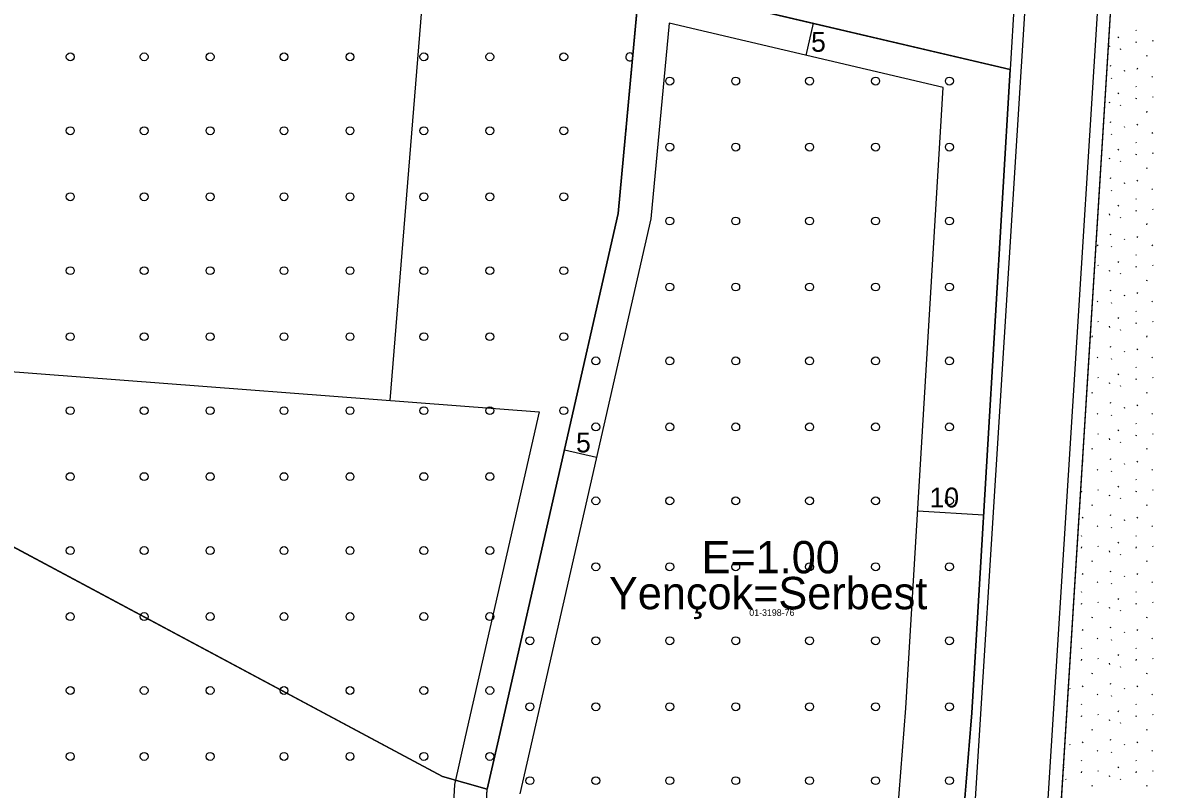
# Model space of a CAD drawing. Extents: x 419396 to 421519, y 4453567 to 4456767.
# Drawn here: x 420389.1 to 420561.7, y 4455467.4 to 4455583.5 of the extents above; entities that cross this region are included whole.
import ezdxf

# ---------------------------------------------------------------- set-up
doc = ezdxf.new("R2010")
doc.units = 0
for name, color, linetype in [('0_KADASTRO', 7, 'Continuous'), ('@PL', 7, 'Continuous'), ('ADAKENARI1000', 7, 'Continuous'), ('F_YAPI_YAKLAŞMA', 7, 'Continuous'), ('KALDIRIM', 7, 'Continuous'), ('Level 33', 7, 'Continuous'), ('Level 41', 7, 'Continuous')]:
    doc.layers.add(name, color=color, linetype=linetype)

msp = doc.modelspace()

# ---------------------------------------------------------------- linework, layer by layer
at = {"layer": '0_KADASTRO'}
for p, q in [((420452.76, 4455469.35), (420330.1, 4455534.91)), ((420459.55, 4455467.41), (420452.76, 4455469.35)), ((420458.85, 4455454.77), (420459.55, 4455467.41))]:
    msp.add_line(p, q, dxfattribs=at)
for points in [[(420545.42, 4455447.04), (420561.03, 4455696.59), (420608.27, 4455685.53), (420614.84, 4455734.09), (420621.11, 4455745.07), (420621.38, 4455786.21), (420636.29, 4455823.29), (420701.58, 4455861.23), (420708.62, 4455863.92), (420715.79, 4455864.57), (420723.78, 4455862.78), (420730.13, 4455859.19), (420735, 4455853.4), (420771.9, 4455797.51), (420787.06, 4455778.4), (420884.04, 4455668.02), (420888.93, 4455658.72), (420890.16, 4455653.06), (420890.46, 4455645.52), (420886.58, 4455581.52), (420884.98, 4455552.19), (420718.56, 4455563.04), (420710.4, 4455437.34), (420549.3, 4455446.81)], [(420275.85, 4455671.09), (420269.39, 4455564.37), (420295.04, 4455552.07), (420330.1, 4455534.91), (420452.76, 4455469.35), (420459.55, 4455467.41), (420461.1, 4455474.22), (420479.42, 4455554.65), (420482.66, 4455589.64), (420486.7, 4455626.91), (420281.84, 4455680.27)], [(420458.85, 4455454.77), (420459.55, 4455467.41), (420461.1, 4455474.22), (420479.42, 4455554.65), (420482.66, 4455589.64), (420538.83, 4455576.49), (420533.01, 4455478.98), (420530.71, 4455450.63), (420530.12, 4455445.17), (420528.73, 4455440.39), (420525.87, 4455433.63)]]:
    msp.add_lwpolyline(points, close=True, dxfattribs=at)
at = {"layer": 'ADAKENARI1000'}
for p, q in [((420545.42, 4455447.04), (420561.03, 4455696.59)), ((420544.5, 4455671.29), (420538.83, 4455576.49)), ((420482.66, 4455589.65), (420479.42, 4455554.65)), ((420538.83, 4455576.49), (420482.66, 4455589.65)), ((420533.01, 4455478.98), (420538.83, 4455576.49)), ((420479.42, 4455554.65), (420461.1, 4455474.22)), ((420530.71, 4455450.63), (420533.01, 4455478.98)), ((420461.1, 4455474.22), (420459.55, 4455467.41))]:
    msp.add_line(p, q, dxfattribs=at)
at = {"layer": 'F_YAPI_YAKLAŞMA'}
for p, q in [((420451.96, 4455614.64), (420444.78, 4455526.32)), ((420487.11, 4455583.47), (420484.37, 4455553.86)), ((420528.65, 4455573.74), (420487.11, 4455583.47)), ((420507.88, 4455578.6), (420509.02, 4455583.47)), ((420523.03, 4455479.68), (420528.65, 4455573.74)), ((420484.37, 4455553.86), (420465.97, 4455473.11)), ((420302.87, 4455537.14), (420467.44, 4455524.59)), ((420467.44, 4455524.59), (420456.23, 4455475.33)), ((420476.13, 4455517.69), (420471.25, 4455518.8)), ((420524.82, 4455509.58), (420534.8, 4455508.98)), ((420520.76, 4455451.57), (420523.03, 4455479.68)), ((420456.23, 4455475.33), (420454.58, 4455468.1)), ((420465.97, 4455473.11), (420464.51, 4455466.71)), ((420454.58, 4455468.1), (420453.79, 4455453.91))]:
    msp.add_line(p, q, dxfattribs=at)
at = {"layer": 'KALDIRIM'}
for p, q in [((420532.5, 4455448.73), (420548.29, 4455701.05)), ((420543.48, 4455448.05), (420559.3, 4455700.93))]:
    msp.add_line(p, q, dxfattribs=at)
at = {"layer": 'Level 33'}
for centre in [(420396.35, 4455578.38), (420407.55, 4455578.38), (420417.55, 4455578.38), (420428.75, 4455578.38), (420438.75, 4455578.38), (420449.95, 4455578.38), (420459.95, 4455578.38), (420471.15, 4455578.38), (420487.22, 4455574.71), (420497.22, 4455574.71), (420508.42, 4455574.71), (420518.42, 4455574.71), (420529.62, 4455574.71), (420396.35, 4455567.18), (420407.55, 4455567.18), (420417.55, 4455567.18), (420428.75, 4455567.18), (420438.75, 4455567.18), (420449.95, 4455567.18), (420459.95, 4455567.18), (420471.15, 4455567.18), (420487.22, 4455564.71), (420497.22, 4455564.71), (420508.42, 4455564.71), (420518.42, 4455564.71), (420529.62, 4455564.71), (420396.35, 4455557.18), (420407.55, 4455557.18), (420417.55, 4455557.18), (420428.75, 4455557.18), (420438.75, 4455557.18), (420449.95, 4455557.18), (420459.95, 4455557.18), (420471.15, 4455557.18), (420487.22, 4455553.51), (420497.22, 4455553.51), (420508.42, 4455553.51), (420518.42, 4455553.51), (420529.62, 4455553.51), (420396.35, 4455545.98), (420407.55, 4455545.98), (420417.55, 4455545.98), (420428.75, 4455545.98), (420438.75, 4455545.98), (420449.95, 4455545.98), (420459.95, 4455545.98), (420471.15, 4455545.98), (420487.22, 4455543.51), (420497.22, 4455543.51), (420508.42, 4455543.51), (420518.42, 4455543.51), (420529.62, 4455543.51), (420396.35, 4455535.98), (420407.55, 4455535.98), (420417.55, 4455535.98), (420428.75, 4455535.98), (420438.75, 4455535.98), (420449.95, 4455535.98), (420459.95, 4455535.98), (420471.15, 4455535.98), (420476.02, 4455532.31), (420487.22, 4455532.31), (420497.22, 4455532.31), (420508.42, 4455532.31), (420518.42, 4455532.31), (420529.62, 4455532.31), (420396.35, 4455524.77), (420407.55, 4455524.77), (420417.55, 4455524.77), (420428.75, 4455524.77), (420438.75, 4455524.77), (420449.95, 4455524.77), (420459.95, 4455524.77), (420471.15, 4455524.77), (420476.02, 4455522.31), (420487.22, 4455522.31), (420497.22, 4455522.31), (420508.42, 4455522.31), (420518.42, 4455522.31), (420529.62, 4455522.31), (420396.35, 4455514.77), (420407.55, 4455514.77), (420417.55, 4455514.77), (420428.75, 4455514.77), (420438.75, 4455514.77), (420449.95, 4455514.77), (420459.95, 4455514.77), (420476.02, 4455511.11), (420487.22, 4455511.11), (420497.22, 4455511.11), (420508.42, 4455511.11), (420518.42, 4455511.11), (420529.62, 4455511.11), (420396.35, 4455503.57), (420407.55, 4455503.57), (420417.55, 4455503.57), (420428.75, 4455503.57), (420438.75, 4455503.57), (420449.95, 4455503.57), (420459.95, 4455503.57), (420476.02, 4455501.11), (420487.22, 4455501.11), (420497.22, 4455501.11), (420508.42, 4455501.11), (420518.42, 4455501.11), (420529.62, 4455501.11), (420396.35, 4455493.57), (420407.55, 4455493.57), (420417.55, 4455493.57), (420428.75, 4455493.57), (420438.75, 4455493.57), (420449.95, 4455493.57), (420459.95, 4455493.57), (420466.02, 4455489.9), (420476.02, 4455489.9), (420487.22, 4455489.9), (420497.22, 4455489.9), (420508.42, 4455489.9), (420518.42, 4455489.9), (420529.62, 4455489.9), (420396.35, 4455482.37), (420407.55, 4455482.37), (420417.55, 4455482.37), (420428.75, 4455482.37), (420438.75, 4455482.37), (420449.95, 4455482.37), (420459.95, 4455482.37), (420466.02, 4455479.9), (420476.02, 4455479.9), (420487.22, 4455479.9), (420497.22, 4455479.9), (420508.42, 4455479.9), (420518.42, 4455479.9), (420529.62, 4455479.9), (420396.35, 4455472.37), (420407.55, 4455472.37), (420417.55, 4455472.37), (420428.75, 4455472.37), (420438.75, 4455472.37), (420449.95, 4455472.37), (420459.95, 4455472.37), (420466.02, 4455468.7), (420476.02, 4455468.7), (420487.22, 4455468.7), (420497.22, 4455468.7), (420508.42, 4455468.7), (420518.42, 4455468.7), (420529.62, 4455468.7)]:
    msp.add_circle(centre, 0.6, dxfattribs=at)
for centre, start, end in [((420481.15, 4455578.38), 33.6502, 315.7609), ((420481.15, 4455567.18), 155.5882, 193.8229)]:
    msp.add_arc(centre, 0.6, start, end, dxfattribs=at)
at = {"layer": 'Level 41'}
for p, q in [((420557.86, 4455582.46), (420557.93, 4455582.36)), ((420555.22, 4455581.27), (420555.29, 4455581.43)), ((420557.92, 4455580.54), (420557.99, 4455580.7)), ((420560.38, 4455580.89), (420560.45, 4455580.78)), ((420553.85, 4455580.1), (420553.87, 4455579.94)), ((420555.48, 4455579.63), (420555.55, 4455579.52)), ((420559.53, 4455578.48), (420559.61, 4455578.64)), ((420554.01, 4455576.95), (420554.08, 4455577.11)), ((420554.12, 4455575.21), (420554.19, 4455575.11)), ((420556.11, 4455576.34), (420556.18, 4455576.23)), ((420558.1, 4455576.54), (420558.17, 4455576.7)), ((420560.32, 4455575.41), (420560.39, 4455575.3)), ((420557.86, 4455573.95), (420557.93, 4455573.85)), ((420553.85, 4455571.59), (420553.87, 4455571.43)), ((420555.22, 4455572.76), (420555.29, 4455572.92)), ((420557.92, 4455572.03), (420557.99, 4455572.19)), ((420560.38, 4455572.38), (420560.45, 4455572.27)), ((420555.48, 4455571.12), (420555.55, 4455571.01)), ((420559.53, 4455569.97), (420559.61, 4455570.13)), ((420554.01, 4455568.44), (420554.08, 4455568.6)), ((420558.1, 4455568.03), (420558.17, 4455568.19)), ((420554.12, 4455566.7), (420554.19, 4455566.6)), ((420556.11, 4455567.83), (420556.18, 4455567.72)), ((420560.32, 4455566.9), (420560.39, 4455566.79)), ((420557.86, 4455565.44), (420557.93, 4455565.34)), ((420553.85, 4455563.08), (420553.87, 4455562.92)), ((420555.22, 4455564.25), (420555.29, 4455564.41)), ((420557.92, 4455563.52), (420557.99, 4455563.68)), ((420560.38, 4455563.87), (420560.45, 4455563.76)), ((420555.48, 4455562.61), (420555.55, 4455562.5)), ((420559.53, 4455561.46), (420559.61, 4455561.62)), ((420554.01, 4455559.93), (420554.08, 4455560.09)), ((420558.1, 4455559.52), (420558.17, 4455559.68)), ((420554.12, 4455558.19), (420554.19, 4455558.09)), ((420556.11, 4455559.32), (420556.18, 4455559.21)), ((420560.32, 4455558.39), (420560.39, 4455558.28)), ((420557.86, 4455556.93), (420557.93, 4455556.83)), ((420553.85, 4455554.57), (420553.87, 4455554.41)), ((420555.22, 4455555.74), (420555.29, 4455555.9)), ((420557.92, 4455555.01), (420557.99, 4455555.17)), ((420560.38, 4455555.36), (420560.45, 4455555.25)), ((420555.48, 4455554.1), (420555.55, 4455553.99)), ((420559.53, 4455552.95), (420559.61, 4455553.11)), ((420554.01, 4455551.42), (420554.08, 4455551.58)), ((420558.1, 4455551.01), (420558.17, 4455551.17)), ((420552.02, 4455549.88), (420552.09, 4455549.77)), ((420554.12, 4455549.68), (420554.19, 4455549.58)), ((420556.11, 4455550.81), (420556.18, 4455550.7)), ((420560.32, 4455549.88), (420560.39, 4455549.77)), ((420557.86, 4455548.42), (420557.93, 4455548.32)), ((420552.09, 4455546.85), (420552.16, 4455546.74)), ((420553.85, 4455546.06), (420553.87, 4455545.9)), ((420555.22, 4455547.23), (420555.29, 4455547.39)), ((420557.92, 4455546.5), (420557.99, 4455546.66)), ((420560.38, 4455546.85), (420560.45, 4455546.74)), ((420555.48, 4455545.59), (420555.55, 4455545.48)), ((420559.53, 4455544.44), (420559.61, 4455544.6)), ((420554.01, 4455542.91), (420554.08, 4455543.07)), ((420556.11, 4455542.3), (420556.18, 4455542.19)), ((420558.1, 4455542.5), (420558.17, 4455542.66)), ((420552.02, 4455541.37), (420552.09, 4455541.26)), ((420554.12, 4455541.17), (420554.19, 4455541.07)), ((420560.32, 4455541.37), (420560.39, 4455541.26)), ((420555.22, 4455538.72), (420555.29, 4455538.88)), ((420557.86, 4455539.91), (420557.93, 4455539.81)), ((420552.09, 4455538.34), (420552.16, 4455538.23)), ((420553.85, 4455537.55), (420553.87, 4455537.39)), ((420555.48, 4455537.08), (420555.55, 4455536.97)), ((420557.92, 4455537.99), (420557.99, 4455538.15)), ((420560.38, 4455538.34), (420560.45, 4455538.23)), ((420551.24, 4455535.93), (420551.31, 4455536.09)), ((420559.53, 4455535.93), (420559.61, 4455536.09)), ((420554.01, 4455534.4), (420554.08, 4455534.56)), ((420556.11, 4455533.79), (420556.18, 4455533.68)), ((420558.1, 4455533.99), (420558.17, 4455534.15)), ((420552.02, 4455532.86), (420552.09, 4455532.75)), ((420554.12, 4455532.66), (420554.19, 4455532.56)), ((420560.32, 4455532.86), (420560.39, 4455532.75)), ((420555.22, 4455530.21), (420555.29, 4455530.37)), ((420557.86, 4455531.4), (420557.93, 4455531.3)), ((420552.09, 4455529.83), (420552.16, 4455529.72)), ((420553.85, 4455529.04), (420553.87, 4455528.88)), ((420555.48, 4455528.57), (420555.55, 4455528.46)), ((420557.92, 4455529.48), (420557.99, 4455529.64)), ((420560.38, 4455529.83), (420560.45, 4455529.72)), ((420551.24, 4455527.42), (420551.31, 4455527.58)), ((420559.53, 4455527.42), (420559.61, 4455527.58)), ((420554.01, 4455525.89), (420554.08, 4455526.05)), ((420556.11, 4455525.28), (420556.18, 4455525.17)), ((420558.1, 4455525.48), (420558.17, 4455525.64)), ((420552.02, 4455524.35), (420552.09, 4455524.24)), ((420554.12, 4455524.15), (420554.19, 4455524.05)), ((420560.32, 4455524.35), (420560.39, 4455524.24)), ((420555.22, 4455521.7), (420555.29, 4455521.86)), ((420557.86, 4455522.89), (420557.93, 4455522.79)), ((420552.09, 4455521.32), (420552.16, 4455521.21)), ((420553.85, 4455520.53), (420553.87, 4455520.37)), ((420555.48, 4455520.06), (420555.55, 4455519.95)), ((420557.92, 4455520.97), (420557.99, 4455521.13)), ((420560.38, 4455521.32), (420560.45, 4455521.21)), ((420551.24, 4455518.91), (420551.31, 4455519.07)), ((420559.53, 4455518.91), (420559.61, 4455519.07)), ((420549.8, 4455516.97), (420549.87, 4455517.13)), ((420554.01, 4455517.38), (420554.08, 4455517.54)), ((420556.11, 4455516.77), (420556.18, 4455516.66)), ((420558.1, 4455516.97), (420558.17, 4455517.13)), ((420552.02, 4455515.84), (420552.09, 4455515.73)), ((420554.12, 4455515.64), (420554.19, 4455515.54)), ((420560.32, 4455515.84), (420560.39, 4455515.73)), ((420549.63, 4455514.3), (420549.64, 4455514.28)), ((420555.22, 4455513.19), (420555.29, 4455513.35)), ((420557.86, 4455514.38), (420557.93, 4455514.28)), ((420549.63, 4455512.46), (420549.7, 4455512.62)), ((420552.09, 4455512.81), (420552.16, 4455512.7)), ((420553.85, 4455512.02), (420553.87, 4455511.86)), ((420555.48, 4455511.55), (420555.55, 4455511.44)), ((420557.92, 4455512.46), (420557.99, 4455512.62)), ((420560.38, 4455512.81), (420560.45, 4455512.7)), ((420551.24, 4455510.4), (420551.31, 4455510.56)), ((420559.53, 4455510.4), (420559.61, 4455510.56)), ((420549.8, 4455508.46), (420549.87, 4455508.62)), ((420554.01, 4455508.87), (420554.08, 4455509.03)), ((420556.11, 4455508.26), (420556.18, 4455508.15)), ((420558.1, 4455508.46), (420558.17, 4455508.62)), ((420552.02, 4455507.33), (420552.09, 4455507.22)), ((420554.12, 4455507.13), (420554.19, 4455507.03)), ((420560.32, 4455507.33), (420560.39, 4455507.22)), ((420549.57, 4455505.87), (420549.64, 4455505.77)), ((420552.09, 4455504.3), (420552.16, 4455504.19)), ((420555.22, 4455504.68), (420555.29, 4455504.84)), ((420557.86, 4455505.87), (420557.93, 4455505.77)), ((420560.38, 4455504.3), (420560.45, 4455504.19)), ((420549.63, 4455503.95), (420549.7, 4455504.11)), ((420553.85, 4455503.51), (420553.87, 4455503.35)), ((420555.48, 4455503.04), (420555.55, 4455502.93)), ((420557.92, 4455503.95), (420557.99, 4455504.11)), ((420551.24, 4455501.89), (420551.31, 4455502.05)), ((420559.53, 4455501.89), (420559.61, 4455502.05)), ((420549.8, 4455499.95), (420549.87, 4455500.11)), ((420554.01, 4455500.36), (420554.08, 4455500.52)), ((420556.11, 4455499.75), (420556.18, 4455499.64)), ((420558.1, 4455499.95), (420558.17, 4455500.11)), ((420552.02, 4455498.82), (420552.09, 4455498.71)), ((420554.12, 4455498.62), (420554.19, 4455498.52)), ((420560.32, 4455498.82), (420560.39, 4455498.71)), ((420549.57, 4455497.36), (420549.64, 4455497.26)), ((420552.09, 4455495.79), (420552.16, 4455495.68)), ((420555.22, 4455496.17), (420555.29, 4455496.33)), ((420557.86, 4455497.36), (420557.93, 4455497.26)), ((420560.38, 4455495.79), (420560.45, 4455495.68)), ((420549.63, 4455495.44), (420549.7, 4455495.6)), ((420553.85, 4455495), (420553.87, 4455494.84)), ((420555.48, 4455494.53), (420555.55, 4455494.42)), ((420557.92, 4455495.44), (420557.99, 4455495.6)), ((420551.24, 4455493.38), (420551.31, 4455493.54)), ((420559.53, 4455493.38), (420559.61, 4455493.54)), ((420549.8, 4455491.44), (420549.87, 4455491.6)), ((420554.01, 4455491.85), (420554.08, 4455492.01)), ((420556.11, 4455491.24), (420556.18, 4455491.13)), ((420558.1, 4455491.44), (420558.17, 4455491.6)), ((420549.57, 4455488.85), (420549.64, 4455488.75)), ((420552.02, 4455490.31), (420552.09, 4455490.2)), ((420554.12, 4455490.11), (420554.19, 4455490.01)), ((420557.86, 4455488.85), (420557.93, 4455488.75)), ((420560.32, 4455490.31), (420560.39, 4455490.2)), ((420549.63, 4455486.93), (420549.7, 4455487.09)), ((420552.09, 4455487.28), (420552.16, 4455487.17)), ((420555.22, 4455487.66), (420555.29, 4455487.82)), ((420557.92, 4455486.93), (420557.99, 4455487.09)), ((420560.38, 4455487.28), (420560.45, 4455487.17)), ((420553.85, 4455486.49), (420553.87, 4455486.33)), ((420555.48, 4455486.02), (420555.55, 4455485.91)), ((420551.24, 4455484.87), (420551.31, 4455485.03)), ((420559.53, 4455484.87), (420559.61, 4455485.03)), ((420547.82, 4455482.73), (420547.89, 4455482.62)), ((420549.8, 4455482.93), (420549.87, 4455483.09)), ((420554.01, 4455483.34), (420554.08, 4455483.5)), ((420556.11, 4455482.73), (420556.18, 4455482.62)), ((420558.1, 4455482.93), (420558.17, 4455483.09)), ((420549.57, 4455480.34), (420549.64, 4455480.24)), ((420552.02, 4455481.8), (420552.09, 4455481.69)), ((420554.12, 4455481.6), (420554.19, 4455481.5)), ((420557.86, 4455480.34), (420557.93, 4455480.24)), ((420560.32, 4455481.8), (420560.39, 4455481.69)), ((420549.63, 4455478.42), (420549.7, 4455478.58)), ((420552.09, 4455478.77), (420552.16, 4455478.66)), ((420555.22, 4455479.15), (420555.29, 4455479.31)), ((420557.92, 4455478.42), (420557.99, 4455478.58)), ((420560.38, 4455478.77), (420560.45, 4455478.66)), ((420553.85, 4455477.98), (420553.87, 4455477.82)), ((420555.48, 4455477.51), (420555.55, 4455477.4)), ((420551.24, 4455476.36), (420551.31, 4455476.52)), ((420554.01, 4455474.83), (420554.08, 4455474.99)), ((420559.53, 4455476.36), (420559.61, 4455476.52)), ((420547.82, 4455474.22), (420547.89, 4455474.11)), ((420549.8, 4455474.42), (420549.87, 4455474.58)), ((420552.02, 4455473.29), (420552.09, 4455473.18)), ((420556.11, 4455474.22), (420556.18, 4455474.11)), ((420558.1, 4455474.42), (420558.17, 4455474.58)), ((420560.32, 4455473.29), (420560.39, 4455473.18)), ((420549.57, 4455471.83), (420549.64, 4455471.73)), ((420554.12, 4455473.09), (420554.19, 4455472.99)), ((420557.86, 4455471.83), (420557.93, 4455471.73)), ((420546.93, 4455470.64), (420547, 4455470.8)), ((420549.63, 4455469.91), (420549.7, 4455470.07)), ((420552.09, 4455470.26), (420552.16, 4455470.15)), ((420555.22, 4455470.64), (420555.29, 4455470.8)), ((420557.92, 4455469.91), (420557.99, 4455470.07)), ((420560.38, 4455470.26), (420560.45, 4455470.15)), ((420547.19, 4455469), (420547.26, 4455468.89)), ((420553.85, 4455469.47), (420553.87, 4455469.31)), ((420555.48, 4455469), (420555.55, 4455468.89)), ((420551.24, 4455467.85), (420551.31, 4455468.01)), ((420559.53, 4455467.85), (420559.61, 4455468.01))]:
    msp.add_line(p, q, dxfattribs=at)

# ---------------------------------------------------------------- texts
at = {"layer": '0_KADASTRO'}
msp.add_text('01-3198-76', height=1, dxfattribs=at).set_placement((420499.28, 4455493.67))
at = {"layer": '@PL'}
for s, p in [('E=1.00', (420492.05, 4455500.12)), ('Yençok=Serbest', (420478.01, 4455494.68))]:
    msp.add_text(s, height=4.9, dxfattribs=at).set_placement(p)
at = {"layer": 'F_YAPI_YAKLAŞMA'}
for s, p in [('5', (420508.65, 4455579.15)), ('5', (420473.02, 4455518.44)), ('10', (420526.61, 4455510.11))]:
    msp.add_text(s, height=3, dxfattribs=at).set_placement(p)

doc.saveas('drawing.dxf')
